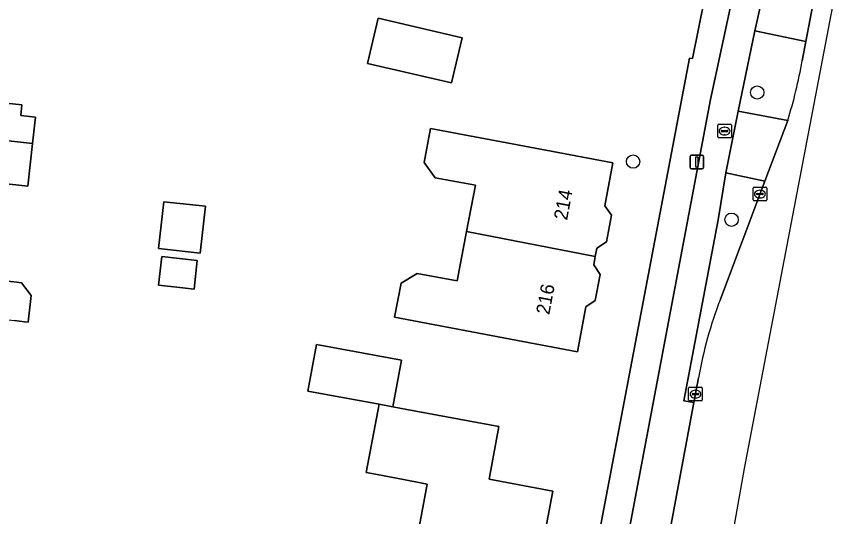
# Model space of a CAD drawing. Extents: x 161258 to 161838, y 380833 to 381727.
# Drawn here: x 161737.5 to 161797.4, y 381382.7 to 381419.3 of the extents above; entities that cross this region are included whole.
import ezdxf

# ---------------------------------------------------------------- set-up
doc = ezdxf.new("R2010")
doc.units = 0
for name, color, linetype in [('IMGEO_Berm_groen', 7, 'Continuous'), ('IMGEO_Boom', 7, 'Continuous'), ('IMGEO_Erf', 7, 'Continuous'), ('IMGEO_Fietspad_open', 7, 'Continuous'), ('IMGEO_Kolk', 7, 'Continuous'), ('IMGEO_Lichtmast', 7, 'Continuous'), ('IMGEO_Pand', 7, 'Continuous'), ('IMGEO_Pand_nummerreeks', 7, 'Continuous'), ('IMGEO_Rijbaan_regionaal_gesloten', 7, 'Continuous'), ('IMGEO_Rioolput', 7, 'Continuous'), ('IMGEO_Verkeerseiland_groen', 7, 'Continuous'), ('IMGEO_Voetpad_open', 7, 'Continuous')]:
    doc.layers.add(name, color=color, linetype=linetype)

msp = doc.modelspace()

# ---------------------------------------------------------------- linework, layer by layer
at = {"layer": 'IMGEO_Berm_groen'}
for points in [[(161792.331, 381407.266), (161789.482, 381407.874), (161788.92, 381404.43), (161786.389, 381391.155), (161787.133, 381391.038), (161787.47, 381392.837)], [(161789.077, 381398.614), (161792.331, 381407.266)]]:
    msp.add_lwpolyline(points, dxfattribs=at)
msp.add_arc((161817.677, 381387.546), 30.667, 158.84445, 170.06539, dxfattribs=at)
at = {"layer": 'IMGEO_Boom'}
for centre in [(161791.774, 381413.755), (161782.678, 381408.689), (161789.893, 381404.432)]:
    msp.add_circle(centre, 0.489, dxfattribs=at)
at = {"layer": 'IMGEO_Erf'}
for points in [[(161712.163, 381347.496), (161746.295, 381343.062), (161749.605, 381342.632), (161772.254, 381339.69), (161786.798, 381416.269), (161787.036, 381416.236), (161788.344, 381422.794), (161783.743, 381423.687), (161780.505, 381424.315), (161777.422, 381424.913), (161778.75, 381431.76), (161775.848, 381432.311), (161776.306, 381434.768), (161782.251, 381433.662), (161783.039, 381437.877), (161784.344, 381444.861), (161780.238, 381445.628), (161780.029, 381444.508), (161772.824, 381445.856)], [(161735.567, 381413.097), (161737.882, 381412.843), (161737.797, 381412.071), (161738.88, 381411.952), (161738.668, 381410.013), (161738.324, 381406.878), (161732.721, 381407.493)], [(161734.516, 381400.175), (161737.512, 381399.846), (161737.653, 381399.831), (161737.857, 381399.809), (161738.567, 381398.88), (161738.352, 381396.922), (161738.085, 381396.952), (161737.346, 381397.034)]]:
    msp.add_lwpolyline(points, dxfattribs=at)
for points in [[(161770.147, 381417.769), (161769.374, 381414.455), (161763.223, 381415.89), (161763.996, 381419.204)], [(161776.288, 381409.535), (161781.201, 381408.61), (161780.607, 381405.455), (161781.083, 381404.76), (161780.717, 381402.82), (161780.021, 381402.344), (161779.905, 381401.728), (161779.791, 381401.121), (161780.265, 381400.427), (161779.904, 381398.509), (161779.21, 381398.034), (161778.593, 381394.755), (161773.68, 381395.68), (161765.199, 381397.277), (161765.671, 381399.783), (161766.849, 381400.497), (161769.786, 381399.94), (161770.476, 381403.579), (161771.117, 381406.955), (161768.18, 381407.512), (161767.353, 381408.613), (161767.826, 381411.128)], [(161751.329, 381405.412), (161750.947, 381401.984), (161747.903, 381402.324), (161748.285, 381405.752)], [(161750.735, 381401.439), (161750.5, 381399.336), (161749.454, 381399.452), (161747.894, 381399.626), (161748.129, 381401.73)], [(161772.844, 381389.277), (161772.118, 381385.422), (161776.791, 381384.539), (161775.234, 381376.303), (161770.322, 381377.232), (161766.263, 381377.999), (161766.33, 381378.356), (161767.586, 381385.049), (161767.219, 381385.119), (161765.849, 381385.38), (161763.911, 381385.748), (161763.533, 381385.82), (161763.122, 381385.898), (161764.068, 381390.901), (161758.838, 381391.869), (161759.471, 381395.29), (161765.709, 381394.135), (161765.076, 381390.715), (161766.095, 381390.526)]]:
    msp.add_lwpolyline(points, close=True, dxfattribs=at)
at = {"layer": 'IMGEO_Fietspad_open'}
msp.add_lwpolyline([(161792.085, 381430.647), (161788.338, 381413.247), (161776.847, 381352.346), (161778.926, 381351.995), (161779.433, 381354.667), (161780.32, 381354.51), (161781.444, 381360.46), (161780.579, 381360.643), (161781.798, 381367.078), (161782.621, 381366.955), (161784.101, 381374.793), (161783.333, 381374.97), (161784.618, 381381.828), (161785.397, 381381.732), (161787.133, 381391.038), (161786.389, 381391.155), (161788.92, 381404.43), (161789.482, 381407.874), (161790.365, 381412.385), (161791.604, 381418.27), (161792.706, 381423.18)], dxfattribs=at)
at = {"layer": 'IMGEO_Kolk'}
for p, q in [((161791.471, 381405.885), (161791.471, 381406.737)), ((161791.546, 381406.811), (161792.398, 381406.811)), ((161791.959, 381406.591), (161791.984, 381406.591)), ((161792.472, 381406.737), (161792.472, 381405.885)), ((161791.73, 381406.305), (161791.73, 381406.317)), ((161792.168, 381406.268), (161791.77, 381406.268)), ((161791.773, 381406.354), (161792.171, 381406.354)), ((161791.982, 381406.031), (161791.957, 381406.031)), ((161792.214, 381406.317), (161792.214, 381406.305)), ((161792.398, 381405.811), (161791.546, 381405.811)), ((161786.747, 381391.225), (161786.747, 381392.077)), ((161786.822, 381392.151), (161787.674, 381392.151)), ((161787.748, 381392.077), (161787.748, 381391.225)), ((161787.006, 381391.645), (161787.006, 381391.657)), ((161787.444, 381391.608), (161787.046, 381391.608)), ((161787.049, 381391.694), (161787.447, 381391.694)), ((161787.235, 381391.931), (161787.26, 381391.931)), ((161787.49, 381391.657), (161787.49, 381391.645)), ((161787.674, 381391.151), (161786.822, 381391.151)), ((161787.258, 381391.371), (161787.233, 381391.371))]:
    msp.add_line(p, q, dxfattribs=at)
for points in [[(161791.471, 381405.885), (161791.471, 381406.737)], [(161791.546, 381406.811), (161792.398, 381406.811)], [(161792.472, 381406.737), (161792.472, 381405.885)], [(161792.398, 381405.811), (161791.546, 381405.811)], [(161786.747, 381391.225), (161786.747, 381392.077)], [(161786.822, 381392.151), (161787.674, 381392.151)], [(161787.748, 381392.077), (161787.748, 381391.225)], [(161787.674, 381391.151), (161786.822, 381391.151)]]:
    msp.add_lwpolyline(points, dxfattribs=at)
for centre, radius, start, end in [((161791.548, 381406.735), 0.0765, 91.55205, 178.44795), ((161791.548, 381406.735), 0.0765, 91.55205, 178.44795), ((161792.396, 381406.735), 0.0765, 1.55205, 88.44795), ((161792.396, 381406.735), 0.0765, 1.55205, 88.44795), ((161791.548, 381405.887), 0.0765, 181.55205, 268.44795), ((161791.548, 381405.887), 0.0765, 181.55205, 268.44795), ((161791.77, 381406.314), 0.0403, 85.87752, 175.75265), ((161791.767, 381406.304), 0.0366, 178.93798, 274.71019), ((161792.171, 381406.311), 0.043, 264.86636, 352.45326), ((161792.175, 381406.316), 0.0386, 1.73085, 96.63898), ((161792.396, 381405.887), 0.0765, 271.55205, 358.44795), ((161792.396, 381405.887), 0.0765, 271.55205, 358.44795), ((161786.824, 381392.075), 0.0765, 91.55205, 178.44795), ((161786.824, 381392.075), 0.0765, 91.55205, 178.44795), ((161787.672, 381392.075), 0.0765, 1.55205, 88.44795), ((161787.672, 381392.075), 0.0765, 1.55205, 88.44795), ((161787.046, 381391.654), 0.0403, 85.87752, 175.75265), ((161787.043, 381391.644), 0.0366, 178.93798, 274.71019), ((161787.447, 381391.651), 0.043, 264.86636, 352.45326), ((161787.451, 381391.656), 0.0386, 1.73085, 96.63898), ((161786.824, 381391.227), 0.0765, 181.55205, 268.44795), ((161786.824, 381391.227), 0.0765, 181.55205, 268.44795), ((161787.672, 381391.227), 0.0765, 271.55205, 358.44795), ((161787.672, 381391.227), 0.0765, 271.55205, 358.44795)]:
    msp.add_arc(centre, radius, start, end, dxfattribs=at)
for centre, major_axis, ratio, start_param, end_param in [((161791.958, 381406.311), (-0.387, 0.002), 0.722429, 4.712389, 7.853982), ((161791.983, 381406.311), (-0.39, 0.002), 0.717154, 1.570796, 4.712389), ((161787.234, 381391.651), (-0.387, 0.002), 0.722429, 4.712389, 7.853982), ((161787.259, 381391.651), (-0.39, 0.002), 0.717154, 1.570796, 4.712389)]:
    msp.add_ellipse(centre, major_axis=major_axis, ratio=ratio, start_param=start_param, end_param=end_param, dxfattribs=at)
at = {"layer": 'IMGEO_Lichtmast'}
for p, q in [((161786.851, 381408.267), (161786.851, 381409.067)), ((161786.851, 381409.067), (161786.851, 381408.267)), ((161786.951, 381409.167), (161787.741, 381409.167)), ((161787.741, 381409.167), (161786.951, 381409.167)), ((161787.841, 381409.067), (161787.841, 381408.267)), ((161787.841, 381408.267), (161787.841, 381409.067)), ((161787.741, 381408.167), (161786.951, 381408.167)), ((161786.951, 381408.167), (161787.741, 381408.167))]:
    msp.add_line(p, q, dxfattribs=at)
msp.add_lwpolyline([(161787.271, 381409.042), (161787.421, 381409.042), (161787.421, 381408.292), (161787.271, 381408.292), (161787.271, 381409.042)], dxfattribs=at)
for centre, start, end in [((161786.951, 381409.067), 90, 180), ((161786.951, 381409.067), 90, 180), ((161787.741, 381409.067), 0, 90), ((161787.741, 381409.067), 360, 90), ((161786.951, 381408.267), 180, 270), ((161786.951, 381408.267), 180, 270), ((161787.741, 381408.267), 270, 0), ((161787.741, 381408.267), 270, 0)]:
    msp.add_arc(centre, 0.1, start, end, dxfattribs=at)
at = {"layer": 'IMGEO_Pand'}
for points in [[(161769.374, 381414.455), (161770.147, 381417.769), (161763.996, 381419.204), (161763.223, 381415.89)], [(161732.709, 381417.1), (161724.855, 381417.975), (161724.734, 381416.871), (161724.019, 381416.297), (161723.885, 381415.071), (161724.46, 381414.354), (161724.161, 381411.63), (161738.668, 381410.013), (161738.88, 381411.952), (161737.797, 381412.071), (161737.882, 381412.843), (161735.567, 381413.097), (161735.815, 381415.35), (161735.033, 381415.436), (161734.361, 381416.184), (161732.629, 381416.374)], [(161732.352, 381404.128), (161732.721, 381407.493), (161738.324, 381406.878), (161738.668, 381410.013), (161724.161, 381411.63), (161723.856, 381408.847), (161723.08, 381408.225), (161722.937, 381406.928), (161723.554, 381406.159), (161723.44, 381405.121)], [(161770.476, 381403.579), (161779.905, 381401.728), (161780.021, 381402.344), (161780.717, 381402.82), (161781.083, 381404.76), (161780.607, 381405.455), (161781.201, 381408.61), (161776.288, 381409.535), (161767.826, 381411.128), (161767.353, 381408.613), (161768.18, 381407.512), (161771.117, 381406.955)], [(161747.903, 381402.324), (161750.947, 381401.984), (161751.329, 381405.412), (161748.285, 381405.752)], [(161732.352, 381404.128), (161723.44, 381405.121), (161723.314, 381403.969), (161722.532, 381403.342), (161722.389, 381402.039), (161723.033, 381401.236), (161722.751, 381398.66), (161737.346, 381397.034), (161738.085, 381396.952), (161738.352, 381396.922), (161738.567, 381398.88), (161737.857, 381399.809), (161737.653, 381399.831), (161737.512, 381399.846), (161734.516, 381400.175), (161734.83, 381403.038), (161732.263, 381403.319)], [(161770.476, 381403.579), (161769.786, 381399.94), (161766.849, 381400.497), (161765.671, 381399.783), (161765.199, 381397.277), (161773.68, 381395.68), (161778.593, 381394.755), (161779.21, 381398.034), (161779.904, 381398.509), (161780.265, 381400.427), (161779.791, 381401.121), (161779.905, 381401.728)], [(161749.454, 381399.452), (161750.5, 381399.336), (161750.735, 381401.439), (161748.129, 381401.73), (161747.894, 381399.626)], [(161764.068, 381390.901), (161765.076, 381390.715), (161765.709, 381394.135), (161759.471, 381395.29), (161758.838, 381391.869)], [(161772.844, 381389.277), (161766.095, 381390.526), (161765.076, 381390.715), (161764.068, 381390.901), (161763.122, 381385.898), (161763.533, 381385.82), (161763.911, 381385.748), (161765.849, 381385.38), (161767.219, 381385.119), (161767.586, 381385.049), (161766.33, 381378.356), (161766.263, 381377.999), (161770.322, 381377.232), (161775.234, 381376.303), (161776.791, 381384.539), (161772.118, 381385.422)]]:
    msp.add_lwpolyline(points, close=True, dxfattribs=at)
at = {"layer": 'IMGEO_Rijbaan_regionaal_gesloten'}
for points in [[(161732.705, 381071.484), (161732.705, 381071.238), (161742.349, 381122.541), (161776.386, 381306.634), (161779.513, 381323.547), (161779.709, 381323.516), (161781.032, 381330.976), (161790.829, 381386.201), (161813.475, 381504.752), (161831.216, 381599.902), (161831.886, 381604.233), (161835.772, 381629.362), (161830.258, 381630.974)], [(161796.39, 381422.991), (161796.287, 381422.496), (161795.324, 381417.493), (161795.062, 381416.071)], [(161794.003, 381411.697), (161792.331, 381407.266), (161789.077, 381398.614)], [(161787.47, 381392.837), (161787.133, 381391.038), (161785.397, 381381.732), (161784.101, 381374.793), (161782.621, 381366.955), (161781.444, 381360.46), (161780.32, 381354.51), (161778.707, 381345.972), (161778.002, 381342.279), (161777.804, 381341.027)]]:
    msp.add_lwpolyline(points, dxfattribs=at)
for centre, radius, start, end in [((161762.053, 381421.748), 33.494, 342.53772, 350.24204), ((161817.677, 381387.546), 30.667, 158.84445, 170.06539)]:
    msp.add_arc(centre, radius, start, end, dxfattribs=at)
at = {"layer": 'IMGEO_Rioolput'}
for p, q in [((161788.875, 381410.5), (161788.875, 381411.352)), ((161788.95, 381411.426), (161789.802, 381411.426)), ((161789.876, 381411.352), (161789.876, 381410.5)), ((161789.134, 381410.92), (161789.134, 381410.932)), ((161789.572, 381410.883), (161789.174, 381410.883)), ((161789.177, 381410.969), (161789.575, 381410.969)), ((161789.386, 381410.646), (161789.361, 381410.646)), ((161789.363, 381411.206), (161789.388, 381411.206)), ((161789.618, 381410.932), (161789.618, 381410.92)), ((161789.802, 381410.426), (161788.95, 381410.426))]:
    msp.add_line(p, q, dxfattribs=at)
for points in [[(161788.875, 381410.5), (161788.875, 381411.352)], [(161788.95, 381411.426), (161789.802, 381411.426)], [(161789.876, 381411.352), (161789.876, 381410.5)], [(161789.802, 381410.426), (161788.95, 381410.426)]]:
    msp.add_lwpolyline(points, dxfattribs=at)
for centre, radius, start, end in [((161788.952, 381411.35), 0.0765, 91.55205, 178.44795), ((161788.952, 381411.35), 0.0765, 91.55205, 178.44795), ((161789.8, 381411.35), 0.0765, 1.55205, 88.44795), ((161789.8, 381411.35), 0.0765, 1.55205, 88.44795), ((161789.174, 381410.929), 0.0403, 85.87752, 175.75265), ((161789.171, 381410.919), 0.0366, 178.93798, 274.71019), ((161789.575, 381410.926), 0.043, 264.86636, 352.45326), ((161789.579, 381410.931), 0.0386, 1.73085, 96.63898), ((161788.952, 381410.502), 0.0765, 181.55205, 268.44795), ((161788.952, 381410.502), 0.0765, 181.55205, 268.44795), ((161789.8, 381410.502), 0.0765, 271.55205, 358.44795), ((161789.8, 381410.502), 0.0765, 271.55205, 358.44795)]:
    msp.add_arc(centre, radius, start, end, dxfattribs=at)
for centre, major_axis, ratio, start_param, end_param in [((161789.362, 381410.926), (-0.387, 0.002), 0.722429, 4.712389, 7.853982), ((161789.387, 381410.926), (-0.39, 0.002), 0.717154, 1.570796, 4.712389)]:
    msp.add_ellipse(centre, major_axis=major_axis, ratio=ratio, start_param=start_param, end_param=end_param, dxfattribs=at)
at = {"layer": 'IMGEO_Verkeerseiland_groen'}
msp.add_lwpolyline([(161795.062, 381416.071), (161795.324, 381417.493), (161791.604, 381418.27), (161790.365, 381412.385), (161794.003, 381411.697)], dxfattribs=at)
msp.add_arc((161762.053, 381421.748), 33.494, 342.53772, 350.24204, dxfattribs=at)
at = {"layer": 'IMGEO_Voetpad_open'}
for points in [[(161774.147, 381338.339), (161776.847, 381352.346), (161788.338, 381413.247), (161792.085, 381430.647), (161795.911, 381451.079), (161805.168, 381500), (161809.91, 381525.057)], [(161804.264, 381506.66), (161803.022, 381500), (161802.977, 381499.759), (161801.672, 381492.76), (161800.413, 381486.006), (161799.06, 381478.747), (161797.827, 381472.131), (161796.574, 381465.41), (161796.482, 381464.918), (161796.391, 381464.426), (161795.043, 381457.163), (161793.753, 381450.216), (161792.476, 381443.339), (161791.179, 381436.353), (161789.916, 381429.55), (161788.651, 381422.734), (161788.344, 381422.794), (161787.036, 381416.236), (161786.798, 381416.269), (161772.254, 381339.69), (161749.605, 381342.632)]]:
    msp.add_lwpolyline(points, dxfattribs=at)
for points in [[(161792.706, 381423.18), (161791.604, 381418.27), (161795.324, 381417.493), (161796.287, 381422.496)], [(161794.003, 381411.697), (161790.365, 381412.385), (161789.482, 381407.874), (161792.331, 381407.266)]]:
    msp.add_lwpolyline(points, close=True, dxfattribs=at)

# ---------------------------------------------------------------- texts
at = {"layer": 'IMGEO_Pand_nummerreeks'}
for s, p in [('214', (161777.834, 381404.348)), ('216', (161776.53, 381397.42))]:
    msp.add_text(s, height=1, rotation=79.33965, dxfattribs=at).set_placement(p)

doc.saveas('drawing.dxf')
